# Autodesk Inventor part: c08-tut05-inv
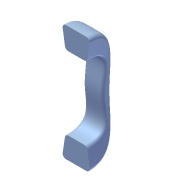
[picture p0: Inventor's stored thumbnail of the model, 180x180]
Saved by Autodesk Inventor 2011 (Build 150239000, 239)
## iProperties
Created: 2010-03
Part Number: c08-tut05-inv
Document SubType Name: Modeling
Designer: CADSoft
Density: 1 g/cm^3
Author: CADSoft
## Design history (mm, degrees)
sketch "Sketch1"
  geometry: L1 (30, 70)-(30, 60); L2 (20, 50)-(-20, 50); L3 (-30, 60)-(-30, 70); A1 r 45 centre (0, 36.459) between (30, 70) and (-30, 70); A2 r 10 centre (-20, 60) between (-30, 60) and (-20, 50); A3 r 10 centre (20, 60) between (20, 50) and (30, 60); 4 further points
  constraints: 6 end point, 6 point on circle, 4 point on line, 4 tangent, 3 centre point, 2 horizontal alignment, 1 coincident, 1 parallel, 1 other
  dimensions: "d4" = 60 distance of point (30, 50) point (-30, 50); "d5" = 30 distance from line of L1 point (0, 0); "d6" = 45 radius of A1; "d7" = 20 distance of point (-30, 50) L3.end; "d8" = 10 radius of A2; "d9" = 10 radius of A3; "d10" = 70 vertical distance of point (0, 0) L3.end
sketch "Sketch2"
  geometry: L1 (40.728, 163.479)-(33.805, 118.479); L2 (23.921, 110)-(-23.921, 110); L3 (-33.805, 118.479)-(-40.728, 163.479); L4 (-30.844, 175)-(30.844, 175); L5 (0, 187.351)-(0, 101.377); A1 r 10 centre (30.844, 165) between (40.728, 163.479) and (30.844, 175); A2 r 10 centre (-30.844, 165) between (-30.844, 175) and (-40.728, 163.479); A3 r 10 centre (-23.921, 120) between (-33.805, 118.479) and (-23.921, 110); A4 r 10 centre (23.921, 120) between (23.921, 110) and (33.805, 118.479); 5 further points
  constraints: 10 end point, 8 point on circle, 8 point on line, 8 tangent, 4 centre point, 3 equal radius, 1 horizontal, 1 parallel, 1 perpendicular
  dimensions: "d11" = 85 distance of point (-42.5, 175) point (42.5, 175); "d12" = 65 distance of point (32.5, 110) point (-32.5, 110); "d13" = 65 distance between parallel lines of L2 L4; "d14" = 175 distance from line of point (0, 0) L4; "d15" = 42.5 horizontal distance of point (0, 0) point (-42.5, 175); "d16" = 32.5 horizontal distance of point (0, 0) point (-32.5, 110); "d17" = 10 radius of A1
sketch "Sketch3"
  geometry: L1 (23.921, -110)-(-23.921, -110); L2 (-33.805, -118.479)-(-40.728, -163.479); L3 (-30.844, -175)-(30.844, -175); L4 (40.728, -163.479)-(33.805, -118.479); A1 r 10 centre (23.921, -120) between (33.805, -118.479) and (23.921, -110); A2 r 10 centre (-23.921, -120) between (-23.921, -110) and (-33.805, -118.479); A3 r 10 centre (-30.844, -165) between (-40.728, -163.479) and (-30.844, -175); A4 r 10 centre (30.844, -165) between (30.844, -175) and (40.728, -163.479); 5 further points
  constraints: 8 end point, 8 point on circle, 8 point on line, 8 tangent, 4 centre point, 3 equal radius, 1 horizontal, 1 parallel
  dimensions: "d18" = 65 distance between parallel lines of L3 L1; "d19" = 65 distance of point (32.5, -110) point (-32.5, -110); "d20" = 85 distance of point (-42.5, -175) point (42.5, -175); "d21" = 32.5 horizontal distance of point (0, 0) point (-32.5, -110); "d22" = 42.5 horizontal distance of point (0, 0) point (-42.5, -175); "d23" = 175 distance from line of point (0, 0) L3; "d24" = 10 radius of A1
loft "Loft1" sketch "Sketch1", "Sketch2", "Sketch3" dims "d25" = 500, "d26" = 90 deg, "d27" = 0, "d28" = 90 deg, "d29" = 500, "d30" = 90 deg
body "Solid1"
